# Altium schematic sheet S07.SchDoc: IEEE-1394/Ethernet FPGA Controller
size 381 x 254 mm; Revision: 3.2; SheetNumber: 7; SheetTotal: 10
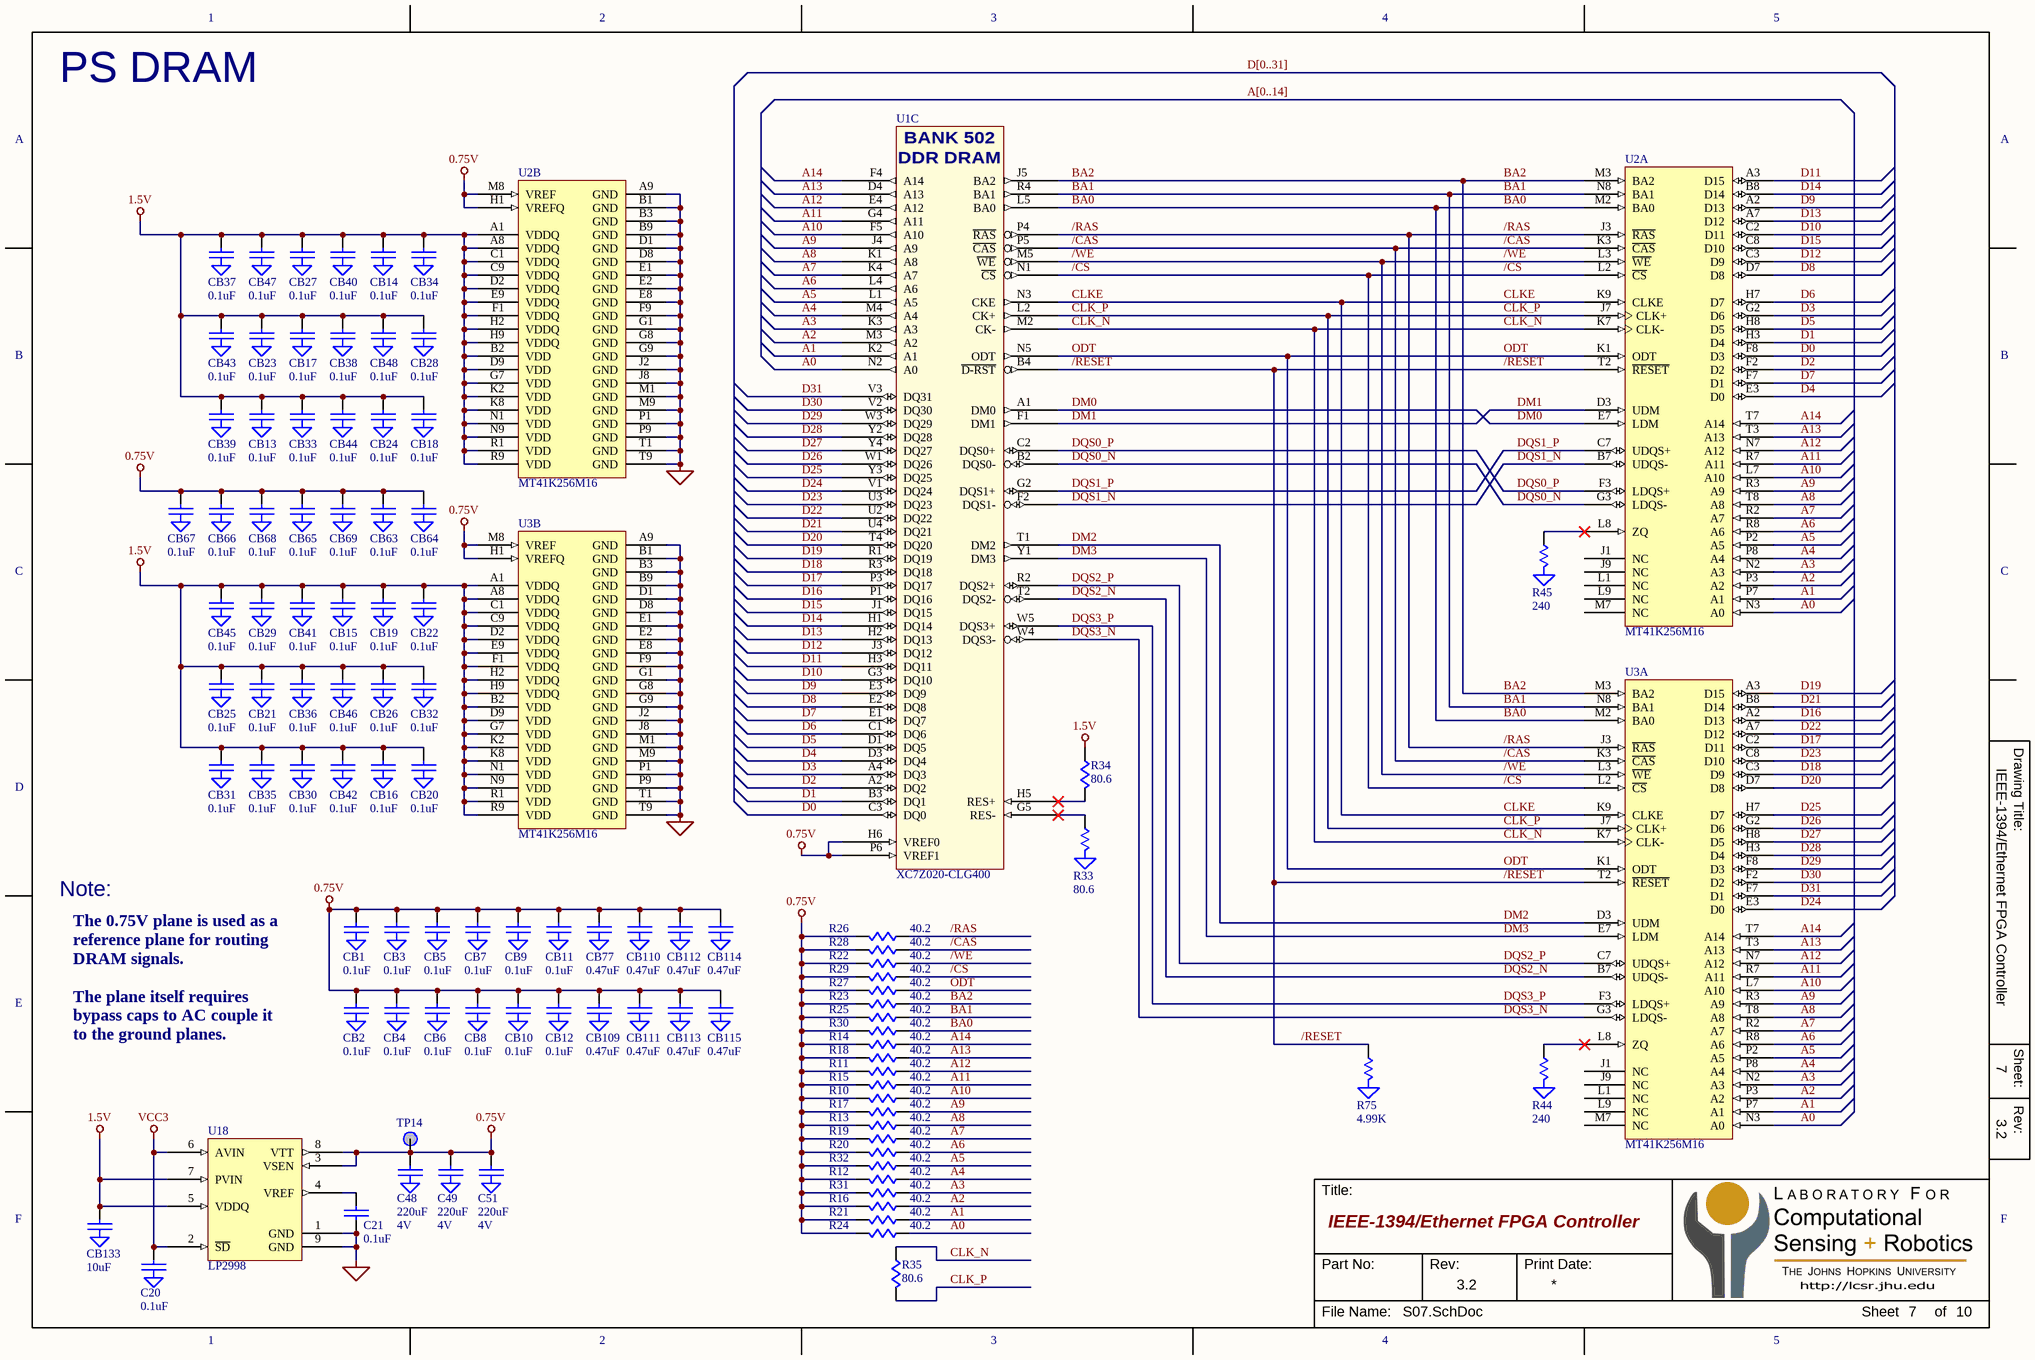
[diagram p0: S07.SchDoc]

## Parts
C20  0.1uF  [C0402]
C21  0.1uF  [C0402]
C48  220uF  [C1206]
C49  220uF  [C1206]
C51  220uF  [C1206]
CB1  0.1uF  [C0201]
CB2  0.1uF  [C0201]
CB3  0.1uF  [C0201]
CB4  0.1uF  [C0201]
CB5  0.1uF  [C0201]
CB6  0.1uF  [C0201]
CB7  0.1uF  [C0201]
CB8  0.1uF  [C0201]
CB9  0.1uF  [C0201]
CB10  0.1uF  [C0201]
CB11  0.1uF  [C0201]
CB12  0.1uF  [C0201]
CB13  0.1uF  [C0201]
CB14  0.1uF  [C0201]
CB15  0.1uF  [C0201]
CB16  0.1uF  [C0201]
CB17  0.1uF  [C0201]
CB18  0.1uF  [C0201]
CB19  0.1uF  [C0201]
CB20  0.1uF  [C0201]
CB21  0.1uF  [C0201]
CB22  0.1uF  [C0201]
CB23  0.1uF  [C0201]
CB24  0.1uF  [C0201]
CB25  0.1uF  [C0201]
CB26  0.1uF  [C0201]
CB27  0.1uF  [C0201]
CB28  0.1uF  [C0201]
CB29  0.1uF  [C0201]
CB30  0.1uF  [C0201]
CB31  0.1uF  [C0201]
CB32  0.1uF  [C0201]
CB33  0.1uF  [C0201]
CB34  0.1uF  [C0201]
CB35  0.1uF  [C0201]
CB36  0.1uF  [C0201]
CB37  0.1uF  [C0201]
CB38  0.1uF  [C0201]
CB39  0.1uF  [C0201]
CB40  0.1uF  [C0201]
CB41  0.1uF  [C0201]
CB42  0.1uF  [C0201]
CB43  0.1uF  [C0201]
CB44  0.1uF  [C0201]
CB45  0.1uF  [C0201]
CB46  0.1uF  [C0201]
CB47  0.1uF  [C0201]
CB48  0.1uF  [C0201]
CB63  0.1uF  [C0201]
CB64  0.1uF  [C0201]
CB65  0.1uF  [C0201]
CB66  0.1uF  [C0201]
CB67  0.1uF  [C0201]
CB68  0.1uF  [C0201]
CB69  0.1uF  [C0201]
CB77  0.47uF  [CB0402]
CB109  0.47uF  [CB0402]
CB110  0.47uF  [CB0402]
CB111  0.47uF  [CB0402]
CB112  0.47uF  [CB0402]
CB113  0.47uF  [CB0402]
CB114  0.47uF  [CB0402]
CB115  0.47uF  [CB0402]
CB133  10uF  [CB0603]
R10  40.2  [R0402]
R11  40.2  [R0402]
R12  40.2  [R0402]
R13  40.2  [R0402]
R14  40.2  [R0402]
R15  40.2  [R0402]
R16  40.2  [R0402]
R17  40.2  [R0402]
R18  40.2  [R0402]
R19  40.2  [R0402]
R20  40.2  [R0402]
R21  40.2  [R0402]
R22  40.2  [R0402]
R23  40.2  [R0402]
R24  40.2  [R0402]
R25  40.2  [R0402]
R26  40.2  [R0402]
R27  40.2  [R0402]
R28  40.2  [R0402]
R29  40.2  [R0402]
R30  40.2  [R0402]
R31  40.2  [R0402]
R32  40.2  [R0402]
R33  80.6  [R0402]
R34  80.6  [R0402]
R35  80.6  [R0402]
R44  240  [R0402]
R45  240  [R0402]
R75  4.99K  [R0402]
TP14  PAD  [PAD25-SM]  (value not drawn)  (no BOM)
U1  XC7Z020-CLG400  [BGA-400-08mm]  (part C of 9)
U2  MT41K256M16  [BGA-96-14x8mm]  (parts A,B of 2)
U3  MT41K256M16  [BGA-96-14x8mm]  (parts A,B of 2)
U18  LP2998  [SO-9]

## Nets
0.75V: C48.1 C49.1 C51.1 CB1.1 CB2.1 CB3.1 CB4.1 CB5.1 CB6.1 CB7.1 CB8.1 CB9.1 CB10.1 CB11.1 CB12.1 CB63.1 CB64.1 CB65.1 CB66.1 CB67.1 CB68.1 CB69.1 CB77.1 CB109.1 CB110.1 CB111.1 CB112.1 CB113.1 CB114.1 CB115.1 R10.2 R11.2 R12.2 R13.2 R14.2 R15.2 R16.2 R17.2 R18.2 R19.2 R20.2 R21.2 R22.2 R23.2 R24.2 R25.2 R26.2 R27.2 R28.2 R29.2 R30.2 R31.2 R32.2 TP14.1 U1.H6(VREF0) U1.P6(VREF1) U2.H1(VREFQ) U2.M8(VREF) U3.H1(VREFQ) U3.M8(VREF) U18.3(VSEN) U18.8(VTT)
1.5V: CB13.1 CB14.1 CB15.1 CB16.1 CB17.1 CB18.1 CB19.1 CB20.1 CB21.1 CB22.1 CB23.1 CB24.1 CB25.1 CB26.1 CB27.1 CB28.1 CB29.1 CB30.1 CB31.1 CB32.1 CB33.1 CB34.1 CB35.1 CB36.1 CB37.1 CB38.1 CB39.1 CB40.1 CB41.1 CB42.1 CB43.1 CB44.1 CB45.1 CB46.1 CB47.1 CB48.1 CB133.1 R34.1 U2.A1(VDDQ) U2.A8(VDDQ) U2.B2(VDD) U2.C1(VDDQ) U2.C9(VDDQ) U2.D2(VDDQ) U2.D9(VDD) U2.E9(VDDQ) U2.F1(VDDQ) U2.G7(VDD) U2.H2(VDDQ) U2.H9(VDDQ) U2.K2(VDD) U2.K8(VDD) U2.N1(VDD) U2.N9(VDD) U2.R1(VDD) U2.R9(VDD) U3.A1(VDDQ) U3.A8(VDDQ) U3.B2(VDD) U3.C1(VDDQ) U3.C9(VDDQ) U3.D2(VDDQ) U3.D9(VDD) U3.E9(VDDQ) U3.F1(VDDQ) U3.G7(VDD) U3.H2(VDDQ) U3.H9(VDDQ) U3.K2(VDD) U3.K8(VDD) U3.N1(VDD) U3.N9(VDD) U3.R1(VDD) U3.R9(VDD) U18.5(VDDQ) U18.7(PVIN)
GND: C20.2(GND) C21.2 C48.2(GND) C49.2(GND) C51.2(GND) CB1.2(GND) CB2.2(GND) CB3.2(GND) CB4.2(GND) CB5.2(GND) CB6.2(GND) CB7.2(GND) CB8.2(GND) CB9.2(GND) CB10.2(GND) CB11.2(GND) CB12.2(GND) CB13.2(GND) CB14.2(GND) CB15.2(GND) CB16.2(GND) CB17.2(GND) CB18.2(GND) CB19.2(GND) CB20.2(GND) CB21.2(GND) CB22.2(GND) CB23.2(GND) CB24.2(GND) CB25.2(GND) CB26.2(GND) CB27.2(GND) CB28.2(GND) CB29.2(GND) CB30.2(GND) CB31.2(GND) CB32.2(GND) CB33.2(GND) CB34.2(GND) CB35.2(GND) CB36.2(GND) CB37.2(GND) CB38.2(GND) CB39.2(GND) CB40.2(GND) CB41.2(GND) CB42.2(GND) CB43.2(GND) CB44.2(GND) CB45.2(GND) CB46.2(GND) CB47.2(GND) CB48.2(GND) CB63.2(GND) CB64.2(GND) CB65.2(GND) CB66.2(GND) CB67.2(GND) CB68.2(GND) CB69.2(GND) CB77.2(GND) CB109.2(GND) CB110.2(GND) CB111.2(GND) CB112.2(GND) CB113.2(GND) CB114.2(GND) CB115.2(GND) CB133.2(GND) R33.2(GND) R44.2(GND) R45.2(GND) R75.2(GND) U2.A9(GND) U2.B1(GND) U2.B3(GND) U2.B9(GND) U2.D1(GND) U2.D8(GND) U2.E1(GND) U2.E2(GND) U2.E8(GND) U2.F9(GND) U2.G1(GND) U2.G8(GND) U2.G9(GND) U2.J2(GND) U2.J8(GND) U2.M1(GND) U2.M9(GND) U2.P1(GND) U2.P9(GND) U2.T1(GND) U2.T9(GND) U3.A9(GND) U3.B1(GND) U3.B3(GND) U3.B9(GND) U3.D1(GND) U3.D8(GND) U3.E1(GND) U3.E2(GND) U3.E8(GND) U3.F9(GND) U3.G1(GND) U3.G8(GND) U3.G9(GND) U3.J2(GND) U3.J8(GND) U3.M1(GND) U3.M9(GND) U3.P1(GND) U3.P9(GND) U3.T1(GND) U3.T9(GND) U18.1(GND) U18.9(GND)
VCC3: C20.1 U18.2(~{SD}) U18.6(AVIN)
/CAS: R28.1 U1.P5(~{CAS}) U2.K3(~{CAS}) U3.K3(~{CAS})
/CS: R29.1 U1.N1(~{CS}) U2.L2(~{CS}) U3.L2(~{CS})
/RAS: R26.1 U1.P4(~{RAS}) U2.J3(~{RAS}) U3.J3(~{RAS})
/RESET: R75.1 U1.B4(~{D-RST}) U2.T2(~{RESET}) U3.T2(~{RESET})
/WE: R22.1 U1.M5(~{WE}) U2.L3(~{WE}) U3.L3(~{WE})
A0: R24.1 U1.N2(A0) U2.N3(A0) U3.N3(A0)
A1: R21.1 U1.K2(A1) U2.P7(A1) U3.P7(A1)
A2: R16.1 U1.M3(A2) U2.P3(A2) U3.P3(A2)
A3: R31.1 U1.K3(A3) U2.N2(A3) U3.N2(A3)
A4: R12.1 U1.M4(A4) U2.P8(A4) U3.P8(A4)
A5: R32.1 U1.L1(A5) U2.P2(A5) U3.P2(A5)
A6: R20.1 U1.L4(A6) U2.R8(A6) U3.R8(A6)
A7: R19.1 U1.K4(A7) U2.R2(A7) U3.R2(A7)
A8: R13.1 U1.K1(A8) U2.T8(A8) U3.T8(A8)
A9: R17.1 U1.J4(A9) U2.R3(A9) U3.R3(A9)
A10: R10.1 U1.F5(A10) U2.L7(A10) U3.L7(A10)
A11: R15.1 U1.G4(A11) U2.R7(A11) U3.R7(A11)
A12: R11.1 U1.E4(A12) U2.N7(A12) U3.N7(A12)
A13: R18.1 U1.D4(A13) U2.T3(A13) U3.T3(A13)
A14: R14.1 U1.F4(A14) U2.T7(A14) U3.T7(A14)
BA0: R30.1 U1.L5(BA0) U2.M2(BA0) U3.M2(BA0)
BA1: R25.1 U1.R4(BA1) U2.N8(BA1) U3.N8(BA1)
BA2: R23.1 U1.J5(BA2) U2.M3(BA2) U3.M3(BA2)
CLK_N: R35.1 U1.M2(CK-) U2.K7(CLK-) U3.K7(CLK-)
CLK_P: R35.2 U1.L2(CK+) U2.J7(CLK+) U3.J7(CLK+)
CLKE: U1.N3(CKE) U2.K9(CLKE) U3.K9(CLKE)
D0: U1.C3(DQ0) U2.F8(D3)
D1: U1.B3(DQ1) U2.H3(D4)
D2: U1.A2(DQ2) U2.F2(D2)
D3: U1.A4(DQ3) U2.G2(D6)
D4: U1.D3(DQ4) U2.E3(D0)
D5: U1.D1(DQ5) U2.H8(D5)
D6: U1.C1(DQ6) U2.H7(D7)
D7: U1.E1(DQ7) U2.F7(D1)
D8: U1.E2(DQ8) U2.D7(D8)
D9: U1.E3(DQ9) U2.A2(D13)
D10: U1.G3(DQ10) U2.C2(D11)
D11: U1.H3(DQ11) U2.A3(D15)
D12: U1.J3(DQ12) U2.C3(D9)
D13: U1.H2(DQ13) U2.A7(D12)
D14: U1.H1(DQ14) U2.B8(D14)
D15: U1.J1(DQ15) U2.C8(D10)
D16: U1.P1(DQ16) U3.A2(D13)
D17: U1.P3(DQ17) U3.C2(D11)
D18: U1.R3(DQ18) U3.C3(D9)
D19: U1.R1(DQ19) U3.A3(D15)
D20: U1.T4(DQ20) U3.D7(D8)
D21: U1.U4(DQ21) U3.B8(D14)
D22: U1.U2(DQ22) U3.A7(D12)
D23: U1.U3(DQ23) U3.C8(D10)
D24: U1.V1(DQ24) U3.E3(D0)
D25: U1.Y3(DQ25) U3.H7(D7)
D26: U1.W1(DQ26) U3.G2(D6)
D27: U1.Y4(DQ27) U3.H8(D5)
D28: U1.Y2(DQ28) U3.H3(D4)
D29: U1.W3(DQ29) U3.F8(D3)
D30: U1.V2(DQ30) U3.F2(D2)
D31: U1.V3(DQ31) U3.F7(D1)
DM0: U1.A1(DM0) U2.E7(LDM)
DM1: U1.F1(DM1) U2.D3(UDM)
DM2: U1.T1(DM2) U3.D3(UDM)
DM3: U1.Y1(DM3) U3.E7(LDM)
DQS0_N: U1.B2(DQS0-) U2.G3(LDQS-)
DQS0_P: U1.C2(DQS0+) U2.F3(LDQS+)
DQS1_N: U1.F2(DQS1-) U2.B7(UDQS-)
DQS1_P: U1.G2(DQS1+) U2.C7(UDQS+)
DQS2_N: U1.T2(DQS2-) U3.B7(UDQS-)
DQS2_P: U1.R2(DQS2+) U3.C7(UDQS+)
DQS3_N: U1.W4(DQS3-) U3.G3(LDQS-)
DQS3_P: U1.W5(DQS3+) U3.F3(LDQS+)
ODT: R27.1 U1.N5(ODT) U2.K1(ODT) U3.K1(ODT)
NetC21_1: C21.1 U18.4(VREF)
NetR33_1: R33.1 U1.G5(RES-)
NetR34_2: R34.2 U1.H5(RES+)
NetR44_1: R44.1 U3.L8(ZQ)
NetR45_1: R45.1 U2.L8(ZQ)

Not connected (* = marked no-connect by the designer): U2 J1(NC) J9(NC) L1(NC) L9(NC) M7(NC); U3 J1(NC) J9(NC) L1(NC) L9(NC) M7(NC)

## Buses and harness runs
bus A[0..14]
bus D[0..31]

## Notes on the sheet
- PS DRAM
- Note:
- The 0.75V plane is used as a reference plane for routing DRAM signals.
  The plane itself requires bypass caps to AC couple it to the ground planes.

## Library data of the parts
C20 C48 C49 C51 CB1-CB48 CB63-CB69 CB77 CB109-CB115 CB133 = CAP-GND
C21 = CAP
R10-R32 R34 R35 = R
R33 R44 R45 R75 = R-GND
